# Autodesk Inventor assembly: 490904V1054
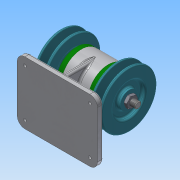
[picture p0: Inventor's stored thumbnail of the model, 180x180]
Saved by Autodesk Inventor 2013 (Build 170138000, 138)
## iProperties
Created: 2019-09
Part Number: 490904V1054
Document SubType Name: Assembly
Designer: Administrator
Author: Administrator
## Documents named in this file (10)
- C:\Users\Administrator\Desktop\490904V1054\490904V1054.iam
- C:\Users\Administrator\Desktop\490904V1054\본체.ipt
- C:\Users\Administrator\Desktop\490904V1054\V-벨트풀리.ipt
- C:\Users\Administrator\Desktop\490904V1054\너트 M10x1.ipt
- C:\Users\Administrator\Desktop\490904V1054\베어링 6004.ipt
- C:\Users\Administrator\Desktop\490904V1054\볼트 M4.ipt
- C:\Users\Administrator\Desktop\490904V1054\오일 실 17 30 5.ipt
- C:\Users\Administrator\Desktop\490904V1054\축.ipt
- C:\Users\Administrator\Desktop\490904V1054\커버.ipt
- C:\Users\Administrator\Desktop\490904V1054\키 5 x 5 x 12.ipt
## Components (2 placed, 1 different names)
1. V-벨트풀리:1
2. V-벨트풀리:2
